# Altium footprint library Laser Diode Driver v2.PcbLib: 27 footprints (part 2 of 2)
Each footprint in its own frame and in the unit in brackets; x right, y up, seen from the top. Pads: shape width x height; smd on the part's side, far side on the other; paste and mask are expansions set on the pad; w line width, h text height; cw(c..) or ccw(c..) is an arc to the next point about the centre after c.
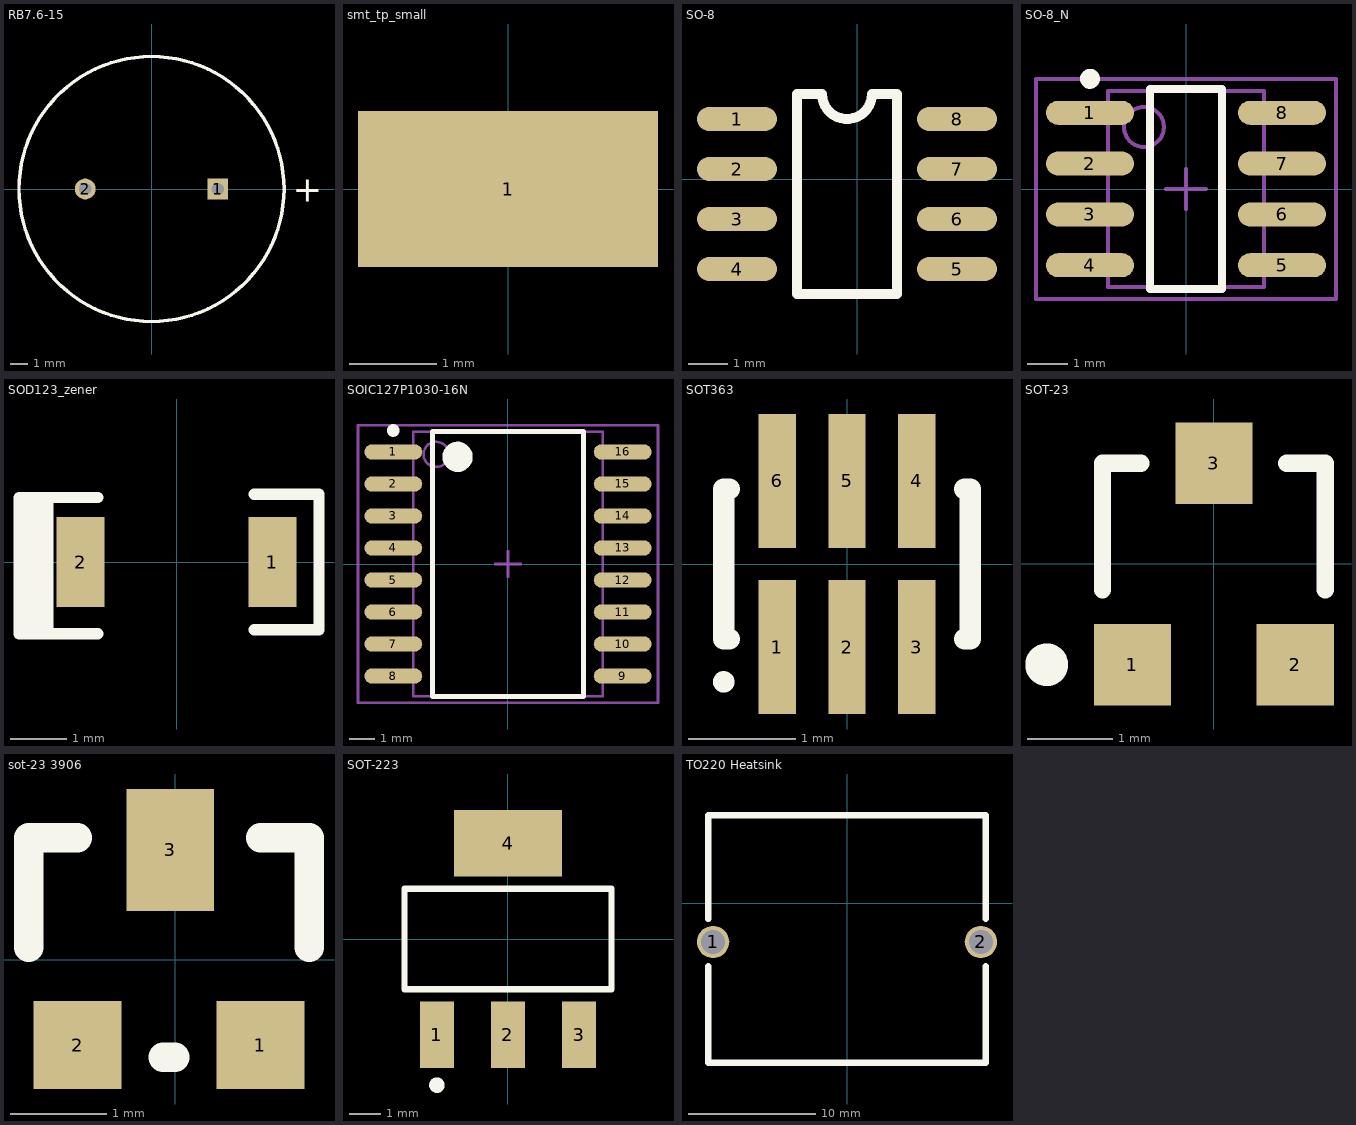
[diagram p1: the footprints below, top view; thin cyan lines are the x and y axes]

## RB7.6-15 [mm] "Polarized Capacitor (Radial); 2 Leads"
height 9.65
pads (2):
  rect 1.2x1.2 hole 0.7: 1(3.81,0)
  round 1.2 hole 0.7: 2(-3.81,0)
Top Overlay:
  circle w0.2: c0,0 r7.62
  text "+" at 8.132,-0.737 h1.5

## smt_tp_small [mil] "Surface Mount Test Point"
height 90
pads (1):
  rect 135x70 smd: 1(0,0)

## SO-8 [mil] "Small Outline 8-pin IC"
height 379.92
pads (8):
  oval 80x24 smd: 1(-120,60) 2(-120,10) 3(-120,-40) 4(-120,-90) 5(100,-90) 6(100,-40) 7(100,10) 8(100,60)
Top Overlay:
  lines w10: -60,-115 40,-115 40,85 15,85 cw(c-10,85) -35,85 -60,85 -60,-115

## SO-8_N [mm] "SOIC, 8-Leads, Body 4.9x3.9mm, Pitch 1.27mm, IPC Medium Density"
height 1.75
pads (8):
  oval 2.2x0.6 smd: 1(-2.4,1.905) 2(-2.4,0.635) 3(-2.4,-0.635) 4(-2.4,-1.905) 5(2.4,-1.905) 6(2.4,-0.635) 7(2.4,0.635) 8(2.4,1.905)
Top Overlay:
  circle w0.25: c-2.4,2.755 r0.125
  lines w0.2: -0.9,-2.5 -0.9,2.5 0.9,2.5 0.9,-2.5 -0.9,-2.5
Mechanical 13:
  circle w0.1: c-1.05,1.55 r0.5
  lines w0.1: -1.95,-2.45 -1.95,2.45 1.95,2.45 1.95,-2.45 -1.95,-2.45
Mechanical 15:
  lines w0.1: -0.5,0 0.5,0 ; 0,-0.5 0,0.5 ; -3.75,-2.75 -3.75,2.75 3.75,2.75 3.75,-2.75 -3.75,-2.75
3D body: height 1.75, standoff 0, extent -1.95,-2.45 1.95,2.45

## SOD123_zener [mm] "footprint for a SOD123 Zener Diode"
pads (2):
  rect 0.85x1.6 smd: 1(1.7,0) 2(-1.7,0)
Top Overlay:
  lines w0.2: -2.667,-1.27 -2.286,-1.27 -1.397,-1.27 ; -2.667,1.143 -2.286,1.143 -1.397,1.143 ; 1.375,-1.2 2.525,-1.2 2.525,1.2 1.375,1.2
  lines w0.203: -2.667,-1.27 -2.667,1.143 -2.794,1.143 -2.794,-1.27 -2.413,-1.27 -2.413,1.143 -2.54,1.143 -2.54,-1.27 ; -2.286,-1.27 -2.286,1.143

## SOIC127P1030-16N [mm] "SOIC, 16-Leads, Body 10.3x7.5mm, Pitch 1.27mm, IPC Medium Density"
height 2.65
pads (16):
  oval 2.3x0.6 smd: 1(-4.55,4.445) 2(-4.55,3.175) 3(-4.55,1.905) 4(-4.55,0.635) 5(-4.55,-0.635) 6(-4.55,-1.905) 7(-4.55,-3.175) 8(-4.55,-4.445) 9(4.55,-4.445) 10(4.55,-3.175) 11(4.55,-1.905) 12(4.55,-0.635) 13(4.55,0.635) 14(4.55,1.905) 15(4.55,3.175) 16(4.55,4.445)
Top Overlay:
  circle w0.6: c-2,4.25 r0.3
  circle w0.25: c-4.55,5.295 r0.125
  lines w0.2: -3,-5.25 3,-5.25 3,5.25 -3,5.25 -3,-5.25
Mechanical 13:
  circle w0.1: c-2.85,4.35 r0.5
  lines w0.1: -3.75,-5.25 3.75,-5.25 3.75,5.25 -3.75,5.25 -3.75,-5.25
Mechanical 15:
  lines w0.1: -0.5,0 0.5,0 ; 0,-0.5 0,0.5 ; -5.95,-5.5 5.95,-5.5 5.95,5.5 -5.95,5.5 -5.95,-5.5
3D body: height 2.65, standoff 0, extent -3.75,-5.25 3.75,5.25

## SOT363 [mm] "SOT-363/SC-88; 6 Leads; Body 2.2 x 2.2 mm, inc. leads (LxW max)"
height 1.1
pads (6):
  rect 0.35x1.25 smd: 1(-0.65,-0.775) 2(0,-0.775) 3(0.65,-0.775) 4(0.65,0.775) 5(0,0.775) 6(-0.65,0.775)
Top Overlay:
  circle w0.1: c-1.15,-1.1 r0.05
  lines w0.2: -1.1,-0.7 -1.15,-0.7 -1.15,0.7 -1.1,0.7 ; 1.1,-0.7 1.15,-0.7 1.15,0.7 1.1,0.7

## SOT-23 [mm] "SOT-23; 3 Leads; Body 3.1 x 2.5 mm, inc. leads (LxW max)"
height 1.11
pads (3):
  rect 0.9x0.95 smd: 1(-0.95,-1.175) 2(0.95,-1.175) 3(0,1.175)
Top Overlay:
  circle w0.25: c-1.95,-1.175 r0.125
  lines w0.2: -1.3,-0.3 -1.3,1.175 -0.85,1.175 ; 0.85,1.175 1.3,1.175 1.3,-0.3

## sot-23 3906 [mil]
height 379.92
pads (3):
  rect 36x36 smd: 1(35,-35) 2(-40,-35)
  rect 36x50 smd: 3(-2,45)
Top Overlay:
  lines w12: -60,5 -60,50 -40,50 ; -5,-40 0,-40 ; 35,50 55,50 55,5

## SOT-223 [mm] "SOT-223/SC-73; 4 Leads; Body 6.7 x 7.3 mm, inc. leads (LxW max)"
height 1.8
pads (4):
  rect 1.1x2.15 smd: 1(-2.3,-3.1) 2(0,-3.1) 3(2.3,-3.1)
  rect 3.5x2.15 smd: 4(0,3.1)
Top Overlay:
  circle w0.25: c-2.3,-4.725 r0.125
  lines w0.2: -3.35,-1.625 3.35,-1.625 3.35,1.625 -3.35,1.625 -3.35,-1.625

## TO220 Heatsink [mil] "HS355-ND"
height 100
pads (2):
  round 100 hole 75: 1(-415,-120) 2(415,-120)
Top Overlay:
  lines w20: -430,-195 -430,-495 430,-495 430,-195 ; -430,-49 -430,273 430,273 430,-48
